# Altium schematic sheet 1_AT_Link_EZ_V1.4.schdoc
size 309 x 223 mm; Symbol: Artery_A4; Device: Artery_A4; Company: Artery Technology; Drawed: SD; Version: 1.2; Page Size: A4; @Project Name: AT_START_F421_V1.2; @Page Count: 4; @Update Date: 2023-09-07; @Schematic Name: AT_START_F421; @Page No: 1; @Page Name: AT_Link_EZ_V1.4
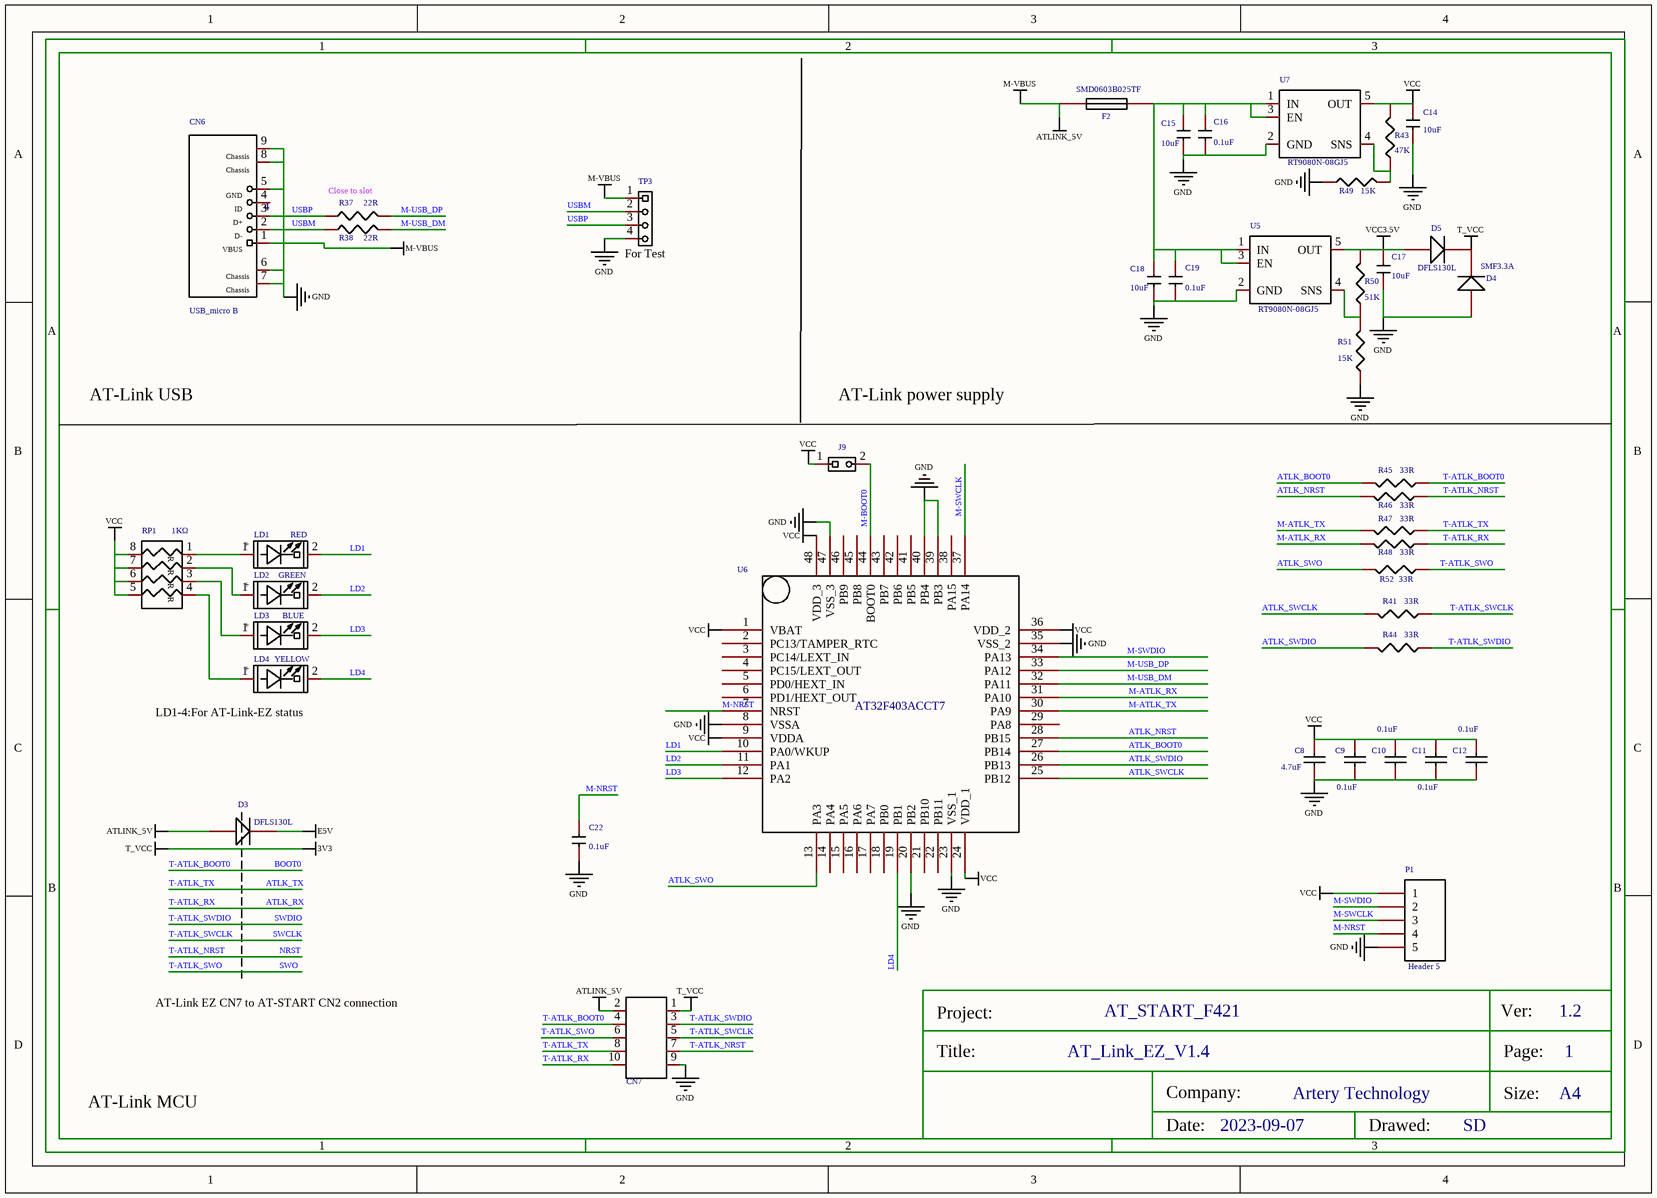
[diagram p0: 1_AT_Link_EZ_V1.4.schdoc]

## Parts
C8  4.7uF  [C0603]
C9  0.1uF  [C0603]
C10  0.1uF  [C0603]
C11  0.1uF  [C0603]
C12  0.1uF  [C0603]
C14  10uF  [C0603]
C15  10uF  [C0603]
C16  0.1uF  [C0603]
C17  10uF  [C0603]
C18  10uF  [C0603]
C19  0.1uF  [C0603]
C22  0.1uF  [C0603]
CN6  NUMBER: 4  [USB_MIC_DIP]  (hidden comment: USB_micro B)
CN7  CON10  [HDR2X5]  (value not drawn)
D3  DFLS130L  [SOD-123]
D4  SMF3.3A  [SOD-123]
D5  DFLS130L  [SOD-123]
F2  SMD0603B025TF  [r0603]
J9  1X2P_2.54M  [HDR1X2]  (value not drawn)
LD1  RED  [LED0603]
LD2  GREEN  [LED0603]
LD3  BLUE  [LED0603]
LD4  YELLOW  [LED0603]
P1  Header 5  [HDR1X5]
R37  22R  [r0603]
R38  22R  [r0603]
R41  33R  [r0603]
R43  47K  [r0603]
R44  33R  [r0603]
R45  33R  [r0603]
R46  33R  [r0603]
R47  33R  [r0603]
R48  33R  [r0603]
R49  15K  [r0603]
R50  51K  [r0603]
R51  15K  [r0603]
R52  33R  [r0603]
RP1  1KΩ  [RP_4-0603]
TP3  1X4P_2.54F  [HDR1X4 - top]  (value not drawn)
U5  RT9080N-08GJ5  [SOT-23-5]
U6  AT32F403ACCT7  [LQFP48 - 2]
U7  RT9080N-08GJ5  [SOT-23-5]

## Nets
3V3: CN7.1 D4.2(K) D5.2(K)  [also labelled T_VCC]
ATLINK_5V: CN6.1(VBUS) CN7.2 D3.1(A) F2.1 TP3.1  [also labelled M-VBUS]
E5V: D3.2(K)
GND: C8.1 C9.1 C10.1 C11.1 C12.1 C14.2 C15.2 C16.2 C17.2 C18.2 C19.2 C22.2 CN6.5(GND) CN6.6 CN6.7 CN6.8 CN6.9 CN7.9 D4.1(A) P1.5 R49.1 R51.1 TP3.4 U5.2(GND) U6.8(VSSA) U6.20(PB2) U6.23(VSS_1) U6.35(VSS_2) U6.39(PB3) U6.40(PB4) U6.47(VSS_3) U7.2(GND)
VCC: C8.2 C9.2 C10.2 C11.2 C12.2 C14.1 J9.1 P1.1 R43.2 RP1.5 RP1.6 RP1.7 RP1.8 U6.1(VBAT) U6.9(VDDA) U6.24(VDD_1) U6.36(VDD_2) U6.48(VDD_3) U7.5(OUT)
VCC3.5V: C17.1 D5.1(A) R50.2 U5.5(OUT)
ATLK_BOOT0: R45.2 U6.27(PB14)
ATLK_NRST: R46.2 U6.28(PB15)
ATLK_RX: CN7.10 R48.1  [also labelled T-ATLK_RX]
ATLK_SWCLK: R41.2 U6.25(PB12)
ATLK_SWDIO: R44.2 U6.26(PB13)
ATLK_SWO: R52.2 U6.13(PA3)
ATLK_TX: CN7.8 R47.1  [also labelled T-ATLK_TX]
BOOT0: CN7.4 R45.1  [also labelled T-ATLK_BOOT0]
LD1: LD1.2(CATHODE) U6.10(PA0/WKUP)
LD2: LD2.2(CATHODE) U6.11(PA1)
LD3: LD3.2(CATHODE) U6.12(PA2)
LD4: LD4.2(CATHODE) U6.19(PB1)
M-ATLK_RX: R48.2 U6.31(PA10)
M-ATLK_TX: R47.2 U6.30(PA9)
M-BOOT0: J9.2 U6.44(BOOT0)
M-NRST: C22.1 P1.4 U6.7(NRST)
M-SWCLK: P1.3 U6.37(PA14)
M-SWDIO: P1.2 U6.34(PA13)
M-USB_DM: R38.2 U6.32(PA11)
M-USB_DP: R37.2 U6.33(PA12)
NRST: CN7.7 R46.1  [also labelled T-ATLK_NRST]
SWCLK: CN7.5 R41.1  [also labelled T-ATLK_SWCLK]
SWDIO: CN7.3 R44.1  [also labelled T-ATLK_SWDIO]
SWO: CN7.6 R52.1  [also labelled T-ATLK_SWO]
USBM: CN6.2(D-) R38.1 TP3.2
USBP: CN6.3(D+) R37.1 TP3.3
NetC15_1: C15.1 C16.1 C18.1 C19.1 F2.2 U5.1(IN) U5.3(EN) U7.1(IN) U7.3(EN)
NetLD1_1: LD1.1(ANODE) RP1.1
NetLD2_1: LD2.1(ANODE) RP1.2
NetLD3_1: LD3.1(ANODE) RP1.3
NetLD4_1: LD4.1(ANODE) RP1.4
NetR43_1: R43.1 R49.2 U7.4(SNS)
NetR50_1: R50.1 R51.2 U5.4(SNS)

Not connected (* = marked no-connect by the designer): CN6 4(ID); U6 2(PC13/TAMPER_RTC) 3(PC14/LEXT_IN) 4(PC15/LEXT_OUT) 5(PD0/HEXT_IN) 6(PD1/HEXT_OUT) 14(PA4) 15(PA5) 16(PA6) 17(PA7) 18(PB0) 21(PB10) 22(PB11) 29(PA8) 38(PA15) 41(PB5) 42(PB6) 43(PB7) 45(PB8) 46(PB9)

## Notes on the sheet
- Close to slot
- (near TP3) For Test
- AT-Link USB
- AT-Link power supply
- (near LD4) LD1-4:For AT-Link-EZ status
- AT-Link EZ CN7 to AT-START CN2 connection
- AT-Link MCU

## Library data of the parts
C8 = 4.7uF/16V: Capacitor (Semiconductor SIM Model); Symbol: Cap Semi; Origin Footprint 2: 0603; Origin Footprint 3: 0402; Origin Footprint 4: C2512; Origin Footprint 5: 1608[0603]; Origin Footprint 6: C1210; Add into BOM: yes
C9-C12 = 0.1uF: 贴片陶瓷电容 0.1uF,25V,X5R,10%,0603; Symbol: Cap Semi; Origin Footprint 2: 0603; Origin Footprint 3: 0402; Origin Footprint 4: C2512; Origin Footprint 5: 1608[0603]; Origin Footprint 6: C1210; Add into BOM: yes
C14 C15 C17 C18 = 10uF: 贴片陶瓷电容 10uF,16V,X5R,20%,0603; Symbol: 0.1uF,50V,20%,SMD0603; Add into BOM: yes
C16 C19 C22 = 0.1uF: 贴片陶瓷电容 0.1uF,25V,X5R,10%,0603; Symbol: 0.1uF,50V,20%,SMD0603; Add into BOM: yes
CN6 = USB_micro B: Micro_USB插座 贴片; Symbol: USB_miniAB,SMD_0; Add into BOM: yes; NAME: ID; Pin Type: IN
CN7 = CON10: 简易牛角DC3-10P 双排90度弯插针 2.54mm 2*5P双排 黑色; Symbol: CON10A_0; Add into BOM: yes
D3 D5 = DFLS130L: DIODES DFLS130L-7; Symbol: Diode; Add into BOM: yes
D4 = SMF3.3A: 贴片TVS二级管 SMF3.3A; Symbol: Diode; Add into BOM: yes
F2 = SMD0603B025TF: 可恢复保险丝 SMD0603B025TF; Symbol: Fuse 1; Add into BOM: yes
J9 = 1X2P_2.54M: 单排直插针1*2P 2.54mm（黑色）; Symbol: 1X2P,Male,DIP_2.54; Origin Footprint 2: SIP_2P; Add into BOM: yes
LD1 = RED: 贴片LED 红色  0603; Symbol: RED,SMD0603; Add into BOM: yes
LD2 = GREEN: 贴片LED 绿色 0603; Symbol: GREEN,SMD0603; Add into BOM: yes
LD3 = BLUE: 贴片LED 蓝色 0603; Symbol: BLUE,SMD0603; Add into BOM: yes
LD4 = YELLOW: 贴片LED 黄色 0603; Symbol: YELLOW,SMD0603; Add into BOM: yes
P1 = Header 5: 单排直插针1*5P 2.54mm （黑色）; Add into BOM: yes
R37 R38 = 22R: 贴片电阻22R,1/10W,5%,0603; Symbol: 22,1/10W,1%,SMD0603; Add into BOM: yes
R41 R44-R48 R52 = 33R: 贴片电阻33R,1/10W,5%,0603; Symbol: 22,1/10W,1%,SMD0603; Add into BOM: yes
R43 = 47K: 贴片电阻47K,1/10W,1%,0603; Symbol: 470,1/10W,1%,SMD0603; Add into BOM: yes
R49 R51 = 15K: 贴片电阻15K,1/10W,1%,0603; Symbol: 470,1/10W,1%,SMD0603; Add into BOM: yes
R50 = 51K: 贴片电阻51K,1/10W,1%,0603; Symbol: 470,1/10W,1%,SMD0603; Add into BOM: yes
RP1 = 1KΩ: 贴片排阻1K,1/16W,5%,0603_x4,8P4R; Symbol: 22,1/16W,5%,8P4R; Add into BOM: yes
TP3 = 1X4P_2.54F: test point 4x2.54mm; Symbol: 1X4P,Female,DIP_2.54; Origin Footprint 2: SIP_4P; Add into BOM: yes
U5 U7 = RT9080N-08GJ5: Add into BOM: yes
U6 = AT32F403CGT6: Symbol: LQFP48&QFN48; Add into BOM: yes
